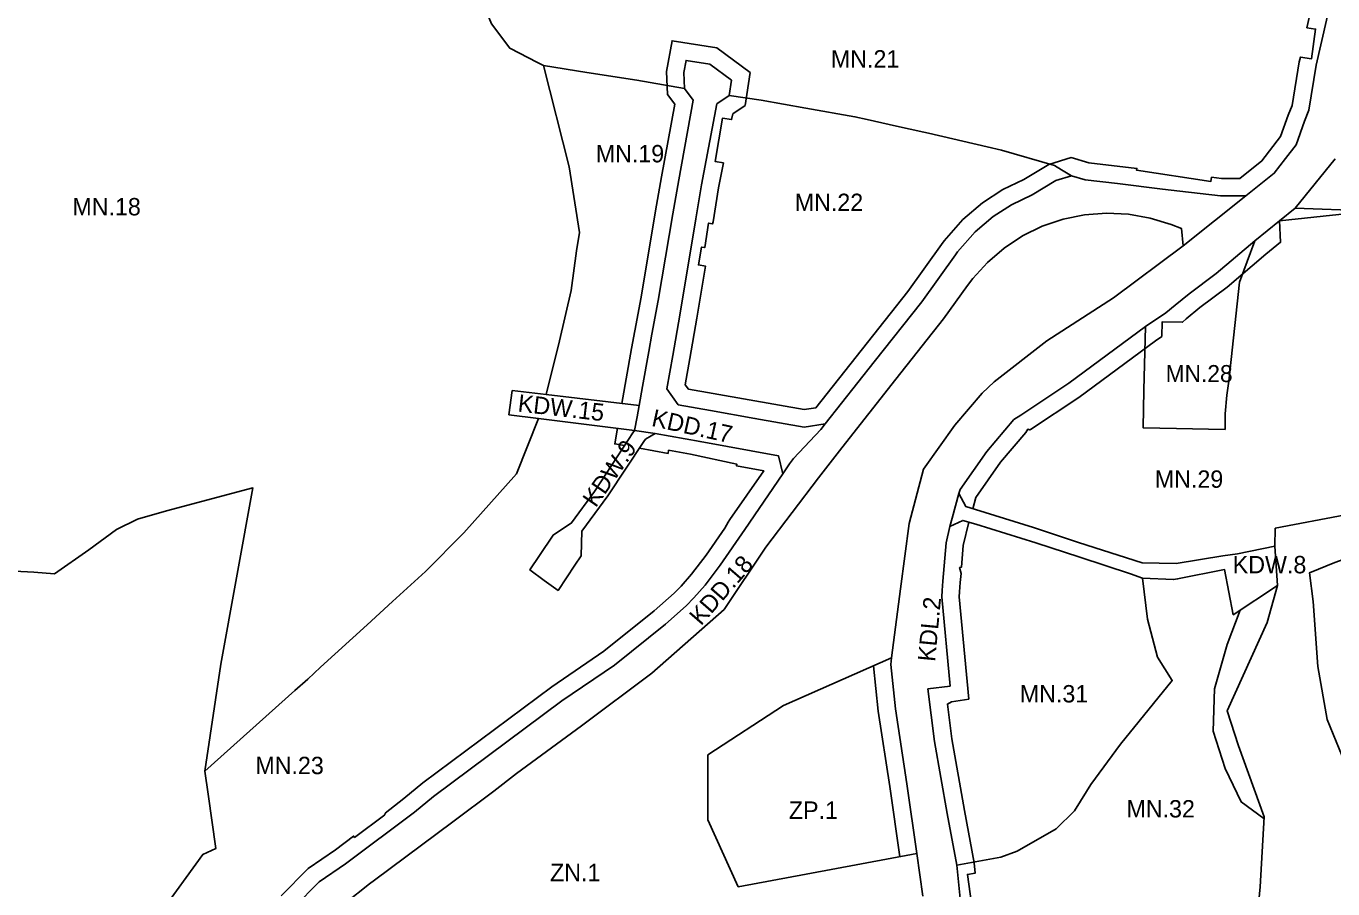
# Model space of a CAD drawing. Extents: x 7414808 to 7417449, y 5544732 to 5546764.
# Drawn here: x 7415519.6 to 7415895.6, y 5545373 to 5545621.3 of the extents above; entities that cross this region are included whole.
import ezdxf

# ---------------------------------------------------------------- set-up
doc = ezdxf.new("R2010")
doc.units = 0
for name, color, linetype in [('LIN_Linie Rozgraniczajace', 7, 'Continuous'), ('LIN_nieprzekraczale linie zabudowy', 7, 'Continuous'), ('TXT_Oznaczenia Przeznaczenia', 7, 'Continuous')]:
    doc.layers.add(name, color=color, linetype=linetype)

msp = doc.modelspace()

# ---------------------------------------------------------------- linework, layer by layer
at = {"layer": 'LIN_Linie Rozgraniczajace'}
for p, q in [((7415852.58, 5545558.06), (7415870.59, 5545572.43)), ((7415658.53, 5545509.45), (7415659.42, 5545516.39))]:
    msp.add_line(p, q, dxfattribs=at)
for points in [[(7415648.98, 5545632.92), (7415650.4, 5545629.46), (7415653.49, 5545621.97), (7415658.73, 5545614.91), (7415666.77, 5545610.81), (7415668.49, 5545609.94)], [(7415870.59, 5545572.43), (7415878.77, 5545578.95), (7415882.02, 5545583.17), (7415885.02, 5545587.08), (7415887.46, 5545593.96), (7415888.71, 5545597.14), (7415890.86, 5545610.04), (7415893.79, 5545623.01), (7415894.95, 5545628.13)], [(7415668.49, 5545609.94), (7415680.91, 5545607.97), (7415695.33, 5545605.69), (7415709.04, 5545603.38)], [(7415669.27, 5545515.25), (7415673.08, 5545530.74), (7415676.4, 5545545.23), (7415677.98, 5545556.65), (7415678.81, 5545561.89), (7415675.81, 5545580.76), (7415668.49, 5545609.94)], [(7415721.9, 5545601.36), (7415722.57, 5545605.71), (7415716.32, 5545610.33), (7415709.49, 5545611.41), (7415708.83, 5545607.92), (7415709.04, 5545603.38)], [(7415694.68, 5545504.95), (7415695.41, 5545508.8), (7415696, 5545512.14), (7415696.96, 5545517.56), (7415698.73, 5545527.63), (7415699.62, 5545532.65), (7415701.45, 5545542.37), (7415705.64, 5545567.27), (7415707.36, 5545577.07), (7415711.52, 5545600.01), (7415709.04, 5545603.38)], [(7415749.54, 5545506.78), (7415743.44, 5545505.89), (7415729.31, 5545508.39), (7415716.53, 5545510.64), (7415707.24, 5545512.28), (7415703.99, 5545516.91), (7415705.65, 5545526.46), (7415707.68, 5545538.08), (7415712.31, 5545565.81), (7415713.91, 5545575.6), (7415718.38, 5545598.92), (7415721.9, 5545601.36)], [(7415721.9, 5545601.36), (7415731.09, 5545599.94), (7415743.94, 5545597.71), (7415758.09, 5545595.2), (7415761.63, 5545594.41), (7415770.06, 5545592.53), (7415777.89, 5545590.81), (7415779.21, 5545590.51), (7415796.11, 5545586.58), (7415800.25, 5545585.56), (7415815.55, 5545581.16), (7415817.54, 5545579.95), (7415820.37, 5545578.24)], [(7415884.74, 5545568.94), (7415896.29, 5545583.07)], [(7415749.54, 5545506.78), (7415763.61, 5545524.68), (7415777.3, 5545541.95), (7415787.02, 5545555.49), (7415787.64, 5545556.34), (7415792.67, 5545562.06), (7415797.82, 5545566.46), (7415803.12, 5545569.9), (7415809.04, 5545572.74), (7415815.94, 5545576.86), (7415820.37, 5545578.24)], [(7415820.37, 5545578.24), (7415824.34, 5545577.08), (7415833.63, 5545575.96), (7415846.59, 5545574.39), (7415851.54, 5545573.82), (7415863.25, 5545572.48), (7415869.23, 5545572.44), (7415870.59, 5545572.43)], [(7415873.18, 5545559.51), (7415880.29, 5545565.29), (7415884.74, 5545568.94)], [(7415884.74, 5545568.94), (7415905.6, 5545568.15), (7415914.76, 5545567.8)], [(7415611.37, 5545368.86), (7415618.38, 5545374.41), (7415619.81, 5545375.45), (7415642.41, 5545392.28), (7415654.17, 5545401.12), (7415660.73, 5545406.18), (7415679.43, 5545419.95), (7415699.67, 5545435.05), (7415720.47, 5545453.39), (7415732.48, 5545471.31), (7415747.57, 5545491.3), (7415754.35, 5545499.95), (7415769.89, 5545519.72), (7415783.58, 5545537), (7415790.52, 5545546.66), (7415792.01, 5545548.62), (7415796.25, 5545553.3), (7415801.05, 5545557.42), (7415806.33, 5545560.9), (7415812, 5545563.68), (7415817.99, 5545565.72), (7415824.18, 5545567), (7415830.48, 5545567.48), (7415836.8, 5545567.16), (7415843.02, 5545566.05), (7415849.05, 5545564.16), (7415852.07, 5545563), (7415852.58, 5545558.06)], [(7415768.65, 5545439.48), (7415771.2, 5545459.35), (7415773.66, 5545478.16), (7415777.86, 5545493.75), (7415786.85, 5545506.49), (7415794.67, 5545515.68), (7415798.11, 5545518.93), (7415813.34, 5545530.76), (7415832.51, 5545543.09), (7415852.58, 5545558.06)], [(7415873.18, 5545559.51), (7415868.71, 5545547.62), (7415865.67, 5545519.13), (7415865.1, 5545515.1), (7415864.62, 5545509.72), (7415864.6, 5545505.58), (7415864.6, 5545505.2), (7415859.8, 5545505.29), (7415850.58, 5545505.45), (7415841.03, 5545505.63), (7415841.23, 5545516.47), (7415841.68, 5545534.85)], [(7415841.68, 5545534.85), (7415847.59, 5545538.78), (7415850.23, 5545540.95), (7415854.22, 5545544.25), (7415862.05, 5545550.11), (7415873.18, 5545559.51)], [(7415787.98, 5545486.77), (7415788.35, 5545487.88), (7415796.05, 5545498.89), (7415803.85, 5545508.04), (7415805.78, 5545509.36), (7415819.64, 5545518.53), (7415841.68, 5545534.85)], [(7415878.92, 5545471.66), (7415879.03, 5545476.77), (7415899.24, 5545480.61), (7415915.42, 5545483.56), (7415916.46, 5545507.74), (7415910.18, 5545508.3), (7415911.47, 5545537.31)], [(7415938.67, 5545534.77), (7415935.27, 5545503.31), (7415933.52, 5545487.35), (7415932.44, 5545480.22), (7415919.83, 5545475.46), (7415896.22, 5545466.89), (7415888.9, 5545463.98), (7415889.93, 5545455.69), (7415891.31, 5545437.02), (7415893.94, 5545421.72), (7415901.72, 5545402.69), (7415907.31, 5545390.02), (7415908.9, 5545386.42), (7415921.31, 5545387.03), (7415938.04, 5545387.87)], [(7415659.42, 5545516.39), (7415669.27, 5545515.25), (7415696, 5545512.14)], [(7415570.97, 5545406.83), (7415596.89, 5545430.04), (7415600.61, 5545433.38), (7415604.31, 5545436.75), (7415617.74, 5545449.02), (7415625.03, 5545455.67), (7415634.47, 5545464.29), (7415645.55, 5545475.44), (7415660.71, 5545492.48), (7415667, 5545508.4)], [(7415700.64, 5545504.03), (7415694.68, 5545504.95), (7415667, 5545508.4), (7415658.53, 5545509.45)], [(7415700.64, 5545504.03), (7415699.46, 5545503.36), (7415697.78, 5545502.4), (7415697.32, 5545501.71), (7415686.95, 5545486.13), (7415679.52, 5545475.92), (7415679.29, 5545468.85), (7415677.46, 5545466.11), (7415672.65, 5545458.86), (7415668.65, 5545461.78), (7415664.57, 5545464.76), (7415667.32, 5545468.91), (7415671.21, 5545474.79), (7415676.56, 5545478.29), (7415683.16, 5545487.32), (7415692.96, 5545502.32), (7415694.19, 5545504.19), (7415694.68, 5545504.95)], [(7415739.3, 5545495.31), (7415740.38, 5545496.86), (7415748.27, 5545505.16), (7415749.54, 5545506.78)], [(7415700.64, 5545504.03), (7415713.51, 5545501.7), (7415736.05, 5545497.64), (7415737.29, 5545492.46)], [(7415586.31, 5545352.83), (7415590.47, 5545359.11), (7415596.75, 5545367.73), (7415603.95, 5545375.04), (7415611.47, 5545380.19), (7415631.3, 5545395.08), (7415636.83, 5545399.56), (7415673.75, 5545427.08), (7415688.85, 5545437.37), (7415703.55, 5545449.17), (7415709.53, 5545454.48), (7415711.75, 5545456.75), (7415714.95, 5545460.36), (7415719.34, 5545466.14), (7415726.4, 5545476.38), (7415737.29, 5545492.46), (7415739.3, 5545495.31)], [(7415490.55, 5545454.78), (7415494.8, 5545459.23), (7415498.58, 5545462.97), (7415498.95, 5545463.34), (7415501.15, 5545465.22), (7415521.79, 5545464.09), (7415527.71, 5545463.61), (7415537.63, 5545470.61), (7415545.57, 5545476.39), (7415551.63, 5545479.42), (7415560, 5545481.81), (7415584.84, 5545488.37), (7415575.63, 5545437.61), (7415570.97, 5545406.83)], [(7415785.39, 5545477.27), (7415786.04, 5545479.66), (7415787.98, 5545486.77)], [(7415787.98, 5545486.77), (7415789.95, 5545483.01), (7415809.44, 5545476.99), (7415822.46, 5545472.71), (7415840.73, 5545466.83), (7415850.52, 5545466.67), (7415863.93, 5545468.81), (7415868.17, 5545469.4), (7415878.92, 5545471.66)], [(7415785.39, 5545477.27), (7415789.15, 5545479.03), (7415792.83, 5545477.91), (7415810.1, 5545472.61), (7415822.76, 5545468.45), (7415837.35, 5545463.64), (7415840.79, 5545462.4)], [(7415785.39, 5545477.27), (7415784.29, 5545472.57), (7415783.42, 5545461.57), (7415783.22, 5545458.89), (7415783.08, 5545457.07), (7415785.46, 5545431.33), (7415779.09, 5545430.53), (7415780.99, 5545415.44), (7415784.66, 5545394.69), (7415787.41, 5545379.82)], [(7415878.92, 5545471.66), (7415879.66, 5545460.27)], [(7415840.79, 5545462.4), (7415849.8, 5545461.99), (7415850.93, 5545462.19), (7415864.44, 5545464.86), (7415866.94, 5545451.9), (7415879.66, 5545460.27)], [(7415787.41, 5545379.82), (7415800.07, 5545382.15), (7415804.74, 5545383.79), (7415815.97, 5545390.31), (7415821.26, 5545395.46), (7415824.71, 5545400.97), (7415825.98, 5545402.99), (7415834.51, 5545414.62), (7415849.39, 5545432.95), (7415845.14, 5545439.7), (7415842.29, 5545450.64), (7415840.79, 5545462.4)], [(7415879.66, 5545460.27), (7415876.71, 5545449.65), (7415865.22, 5545424.25), (7415868.44, 5545414.11), (7415875.83, 5545393.73), (7415874.66, 5545373.55), (7415872.37, 5545349.31), (7415902.54, 5545318.9), (7415903.97, 5545317.38), (7415911.08, 5545297.88), (7415872.14, 5545283.71)], [(7415768.65, 5545439.48), (7415737.48, 5545425.72), (7415715.75, 5545411.55), (7415715.78, 5545392.84), (7415724.5, 5545373.59), (7415744.05, 5545377.23), (7415775.89, 5545383.12)], [(7415775.89, 5545383.12), (7415773.03, 5545403.19), (7415769.76, 5545424.81), (7415768.41, 5545437.6), (7415768.65, 5545439.48)], [(7415558.05, 5545365.8), (7415570.42, 5545382.89), (7415574.17, 5545384.63), (7415571.92, 5545400.24), (7415570.97, 5545406.83)], [(7415775.89, 5545383.12), (7415777.63, 5545370.86)], [(7415787.41, 5545379.82), (7415788.91, 5545364.43), (7415790.69, 5545357.27), (7415793.7, 5545350.68), (7415795.74, 5545348.17), (7415798.73, 5545346.68), (7415808.59, 5545347.3), (7415809.39, 5545335.93), (7415816.77, 5545334.97), (7415834.5, 5545332.86), (7415840.72, 5545332.14), (7415850.71, 5545329.11), (7415864.2, 5545315.19), (7415867.56, 5545307.45), (7415869.94, 5545300.14), (7415872.14, 5545283.71)]]:
    msp.add_lwpolyline(points, dxfattribs=at)
at = {"layer": 'LIN_nieprzekraczale linie zabudowy'}
for points in [[(7415691.02, 5545512.72), (7415693.81, 5545528.5), (7415694.7, 5545533.55), (7415696.53, 5545543.25), (7415700.71, 5545568.12), (7415702.44, 5545577.95), (7415706.23, 5545598.84), (7415704.11, 5545601.61), (7415703.81, 5545608.27), (7415705.48, 5545617.1), (7415718.3, 5545615.08), (7415727.97, 5545607.93), (7415726.51, 5545598.47), (7415722.92, 5545596.02), (7415722.6, 5545594.37), (7415719.98, 5545594.8), (7415717.85, 5545582.33), (7415720.22, 5545581.94), (7415718.83, 5545574.73), (7415717.24, 5545565), (7415717.14, 5545564.37), (7415715.99, 5545564.58), (7415714.87, 5545557.54), (7415713.93, 5545557.7), (7415713.03, 5545552.56), (7415715.1, 5545552.17), (7415712.61, 5545537.24), (7415710.58, 5545525.6), (7415709.27, 5545518.09), (7415710.15, 5545516.84), (7415743.52, 5545510.95), (7415746.86, 5545511.44), (7415773.3, 5545544.96), (7415782.98, 5545558.43), (7415783.74, 5545559.47), (7415789.14, 5545565.63), (7415794.82, 5545570.48), (7415800.67, 5545574.27), (7415806.67, 5545577.15), (7415813.88, 5545581.46), (7415820.32, 5545583.46), (7415825.35, 5545581.99), (7415839.21, 5545580.32), (7415839.13, 5545579.79), (7415860.5, 5545576.56), (7415860.71, 5545577.8), (7415863.55, 5545577.48), (7415868.86, 5545577.44), (7415875.18, 5545582.48), (7415880.57, 5545589.5), (7415882.78, 5545595.71), (7415883.86, 5545598.48), (7415885.95, 5545611), (7415886.26, 5545612.38), (7415889.51, 5545611.92), (7415890.63, 5545620.44), (7415888.17, 5545620.81), (7415888.91, 5545624.11)], [(7415900.02, 5545567.35), (7415880.29, 5545565.23), (7415880.57, 5545559.08), (7415876.37, 5545555.66), (7415865.16, 5545546.2), (7415857.31, 5545540.32), (7415853.41, 5545537.09), (7415852.35, 5545536.07), (7415846.48, 5545536.14), (7415846.41, 5545531.99), (7415844.55, 5545530.76), (7415822.51, 5545514.43), (7415808.57, 5545505.21), (7415808.39, 5545505.09), (7415807.81, 5545505.27), (7415807.22, 5545504.29), (7415800.01, 5545495.83), (7415792.89, 5545485.65), (7415791.99, 5545482.38)], [(7415691.8, 5545500.55), (7415688.97, 5545501.06), (7415689.76, 5545505.56)], [(7415592.93, 5545370.97), (7415600.73, 5545378.89), (7415608.56, 5545384.25), (7415613.81, 5545388.19), (7415614.1, 5545387.8), (7415622.8, 5545394.32), (7415622.86, 5545394.76), (7415628.22, 5545399.02), (7415633.76, 5545403.51), (7415670.85, 5545431.16), (7415685.87, 5545441.39), (7415700.33, 5545452.99), (7415706.08, 5545458.1), (7415708.09, 5545460.15), (7415711.08, 5545463.53), (7415715.29, 5545469.07), (7415720.65, 5545476.84), (7415721.57, 5545478.56), (7415722.06, 5545479.27), (7415731.82, 5545493.32), (7415724.02, 5545494.73), (7415724.1, 5545495.2), (7415710.75, 5545498.08), (7415704.45, 5545499.21), (7415704.29, 5545498.29), (7415696.04, 5545499.78)], [(7415790.82, 5545478.52), (7415789.24, 5545471.8), (7415788.76, 5545465.62), (7415788.21, 5545465.47), (7415788.61, 5545463.79), (7415788.41, 5545461.19), (7415788.21, 5545458.52), (7415788.1, 5545457.07), (7415790.82, 5545427.62), (7415785.92, 5545426.85), (7415784.68, 5545426.19), (7415785.94, 5545416.19), (7415789.58, 5545395.58), (7415792.37, 5545380.52), (7415792.66, 5545377.49), (7415790.43, 5545377.14), (7415791.67, 5545368.8)], [(7415875.8, 5545393.19), (7415869.27, 5545398), (7415864.58, 5545407.6), (7415861.2, 5545418.35), (7415861.52, 5545430.51), (7415865.17, 5545443.31), (7415868.98, 5545453.24)], [(7415770.96, 5545382.21), (7415768.08, 5545402.46), (7415764.8, 5545424.17), (7415763.43, 5545437.17)]]:
    msp.add_lwpolyline(points, dxfattribs=at)

# ---------------------------------------------------------------- texts
at = {"layer": 'TXT_Oznaczenia Przeznaczenia'}
for s, height, p in [('MN.21', 5, (7415751.16, 5545609.37)), ('MN.19', 5, (7415683.49, 5545582.08)), ('MN.22', 5, (7415740.76, 5545568.07)), ('MN.18', 5, (7415532.88, 5545566.82)), ('MN.28', 4.892, (7415847.5, 5545518.85)), ('MN.29', 5, (7415844.38, 5545488.42)), ('KDW.8', 5, (7415866.81, 5545463.8)), ('MN.31', 5, (7415805.53, 5545426.64)), ('MN.23', 5, (7415585.54, 5545406)), ('ZP.1', 5, (7415739.08, 5545393.14)), ('MN.32', 5, (7415836.22, 5545393.53)), ('ZN.1', 5, (7415670.35, 5545375.2))]:
    msp.add_text(s, height=height, dxfattribs=at).set_placement(p)
for s, rotation, p in [('KDW.15', 353.4886, (7415660.9, 5545510.38)), ('KDD.17', 347.6289, (7415699.31, 5545506.24)), ('KDW.9', 55.3178, (7415683.49, 5545482.5)), ('KDD.18', 48.9933, (7415713.76, 5545448.53)), ('KDL.2', 84.6361, (7415781.14, 5545438.24))]:
    msp.add_text(s, height=5, rotation=rotation, dxfattribs=at).set_placement(p)

doc.saveas('drawing.dxf')
